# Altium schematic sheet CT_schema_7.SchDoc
size 226 x 144 mm
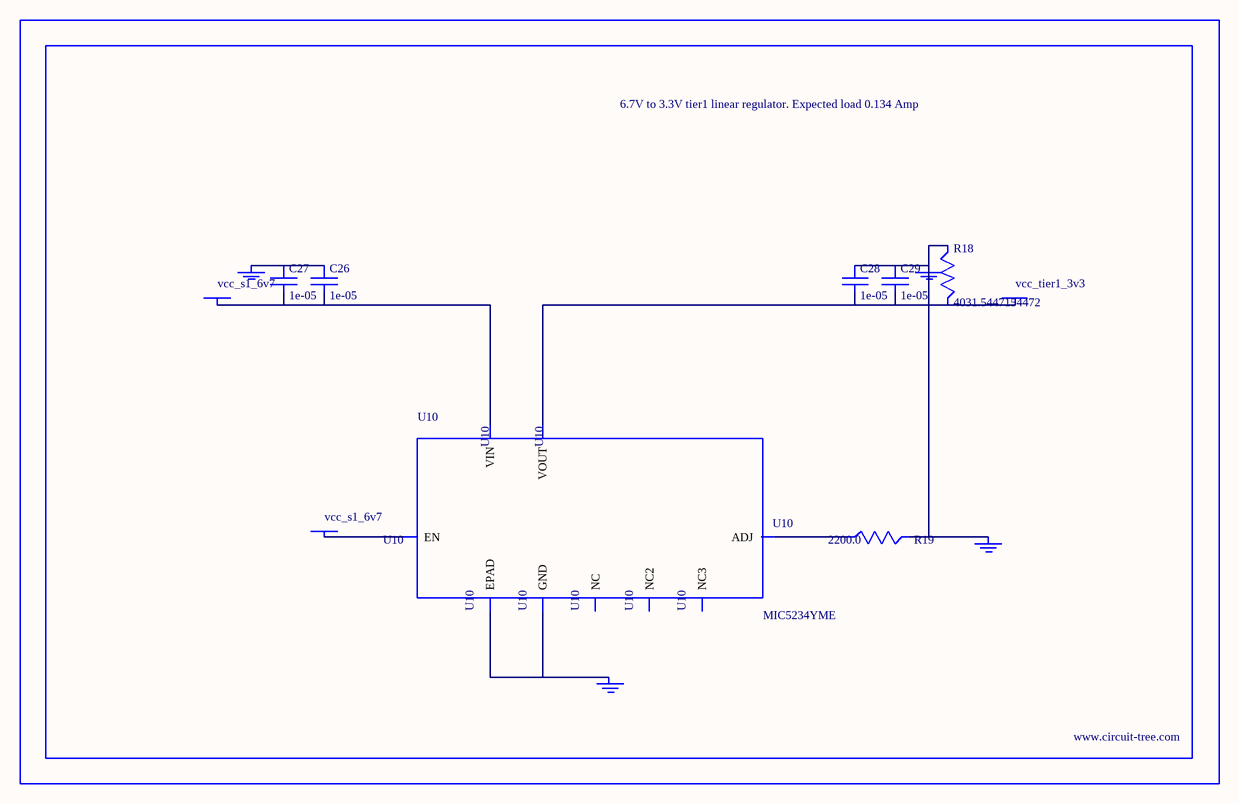
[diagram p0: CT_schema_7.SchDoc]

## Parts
BORDER6  (no value)
C26  1e-05  [C1210]
C27  1e-05  [C1210]
C28  1e-05  [C1210]
C29  1e-05  [C1210]
GND_INSTANCE_6_0  (no value)
GND_INSTANCE_6_1  (no value)
GND_INSTANCE_6_2  (no value)
GND_INSTANCE_6_3  (no value)
POWER_INSTANCE_6_0  vcc_tier1_3v3
POWER_INSTANCE_6_1  vcc_s1_6v7
POWER_INSTANCE_6_2  vcc_s1_6v7
R18  4031.5447154472  [R0603]
R19  2200.0  [R0603]
U10  MIC5234YME  [SOIC-8_EP]

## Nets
NetC26_1: C26.1 C27.1 GND_INSTANCE_6_3.0(GND)
NetC26_2: C26.2 C27.2 POWER_INSTANCE_6_2.0(PWR) U10.8(VIN)
NetC28_1: C28.1 C29.1 GND_INSTANCE_6_0.0(GND) GND_INSTANCE_6_1.0(GND) R18.1 R19.2
NetC28_2: C28.2 C29.2 POWER_INSTANCE_6_0.0(PWR) R18.2 U10.1(VOUT)
NetGND_INSTANCE_6_2_0: GND_INSTANCE_6_2.0(GND) U10.7(GND) U10.EPAD
NetPOWER_INSTANCE_6_1_0: POWER_INSTANCE_6_1.0(PWR) U10.5(EN)
NetR19_1: R19.1 U10.4(ADJ)

Not connected (* = marked no-connect by the designer): U10 2(NC) 3(NC2) 6(NC3)

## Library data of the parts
BORDER6 = BORDER_PAGE6
C26-C29 = C1210C106K5PACTU
GND_INSTANCE_6_0-GND_INSTANCE_6_3 = GND
POWER_INSTANCE_6_0-POWER_INSTANCE_6_2 = PWR
R18 = R18
R19 = RC0603JR-072K2L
